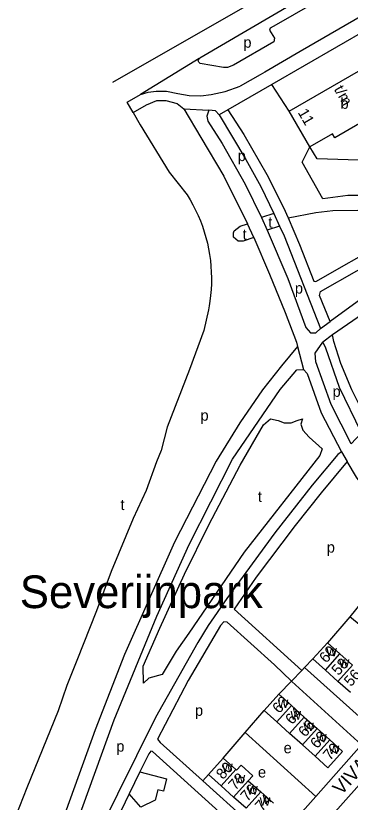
# Model space of a CAD drawing. Extents: x 159045 to 160918, y 380454 to 382516.
# Drawn here: x 159318.3 to 159441.1, y 382048.4 to 382337.4 of the extents above; entities that cross this region are included whole.
import ezdxf

# ---------------------------------------------------------------- set-up
doc = ezdxf.new("R2010")
doc.units = 0
for name, color, linetype in [('BLT_Basislijn', 7, 'Continuous'), ('BLT_Bebouwing', 7, 'Continuous'), ('BLT_Centroide', 7, 'Continuous'), ('BLT_Huisnummer', 7, 'Continuous'), ('BLT_Huisnummer_ tussenligend', 7, 'Continuous'), ('BLT_Huisnummer_reeks', 7, 'Continuous'), ('BLT_Onderverdeling_panden', 7, 'Continuous'), ('BLT_Sport_parknaam', 7, 'Continuous'), ('BLT_Straatnaam', 7, 'Continuous'), ('BLT_Vlakafsluiter', 7, 'Continuous')]:
    doc.layers.add(name, color=color, linetype=linetype)

msp = doc.modelspace()

# ---------------------------------------------------------------- linework, layer by layer
at = {"layer": 'BLT_Basislijn'}
for p, q in [((159494.14, 382393.47), (159353.79, 382312.86)), ((159512.55, 382376.27), (159422.73, 382324.31)), ((159507.03, 382367.04), (159412.29, 382312.23)), ((159420.65, 382342.17), (159385.91, 382321.89)), ((159385.58, 382321.68), (159385.91, 382321.89)), ((159422.73, 382324.31), (159409.73, 382316.76)), ((159409.73, 382316.76), (159407.99, 382315.75)), ((159407.99, 382315.75), (159400.66, 382311.52)), ((159412.29, 382312.23), (159396.13, 382302.88)), ((159418.68, 382302.38), (159412.29, 382312.23)), ((159359.18, 382305.7), (159364.06, 382308.47)), ((159361.4, 382301.85), (159361.31, 382301.8)), ((159396.13, 382302.88), (159392.96, 382301.05)), ((159428.9, 382284.85), (159426.23, 382289.25)), ((159462.69, 382283.81), (159428.9, 382284.85)), ((159374.6, 382279.99), (159381.19, 382271.64)), ((159416.59, 382267.01), (159418.25, 382263.17)), ((159413.01, 382264.77), (159408.52, 382263.36)), ((159413.01, 382264.77), (159415.11, 382260.15)), ((159408.52, 382263.36), (159410.6, 382258.69)), ((159405.64, 382256), (159403.35, 382261)), ((159415.11, 382260.15), (159410.6, 382258.69)), ((159430.17, 382222.56), (159433.75, 382225.1)), ((159434.58, 382220.18), (159431.06, 382217.46)), ((159437.83, 382177.21), (159439.91, 382173.65)), ((159445.62, 382122.3), (159440.87, 382116.62)), ((159440.87, 382116.62), (159432.69, 382107.06)), ((159427.35, 382101.11), (159424.31, 382097.97)), ((159423.26, 382096.88), (159419.49, 382092.97)), ((159424.31, 382097.97), (159423.26, 382096.88)), ((159450.05, 382074.76), (159424.31, 382097.97)), ((159419.49, 382092.97), (159414.82, 382088.15)), ((159402.54, 382074.05), (159409.44, 382082.15)), ((159394.46, 382064.58), (159402.54, 382074.05)), ((159402.54, 382074.05), (159428.38, 382050.54)), ((159445.22, 382069.48), (159428.38, 382050.54)), ((159387.02, 382056.3), (159389.08, 382058.58)), ((159387.02, 382056.3), (159412.8, 382033.08)), ((159322.34, 382053.71), (159318.3, 382043.44)), ((159412.8, 382033.08), (159428.38, 382050.54))]:
    msp.add_line(p, q, dxfattribs=at)
for points in [[(159501.17, 382387.34), (159501.9, 382387.24), (159502.71, 382386.42), (159503.24, 382384.81), (159503.24, 382382.34), (159502.64, 382380.86), (159501.42, 382379.08), (159500.46, 382378.31), (159497.68, 382376.68), (159496.51, 382377.03), (159494.66, 382380.2), (159493.96, 382380.33), (159413.82, 382334.09)], [(159592.57, 382343.04), (159590.44, 382339.54), (159588.26, 382337.01), (159584.78, 382334.23), (159580.18, 382331.31), (159560.97, 382326.03), (159552.16, 382321.45), (159546.85, 382317.26), (159543.9, 382313.98), (159537.31, 382304.44), (159532.38, 382299.35), (159524.92, 382294.23), (159519.04, 382291.75), (159461.4, 382270.09), (159448.2, 382271.36), (159440.22, 382271.36), (159430.99, 382270.17), (159423.36, 382283.59), (159426.23, 382289.25)], [(159418.25, 382263.17), (159428.39, 382265.11), (159434.66, 382265.93), (159443.56, 382265.97), (159459.49, 382265.16), (159462.83, 382265.29), (159508.3, 382282.41), (159524.15, 382288.09), (159528.25, 382289.87), (159532.86, 382292.9), (159538.43, 382297.92), (159542.44, 382303.14), (159547.33, 382310.25), (159553.12, 382315.98), (159556.64, 382318.44), (159564.66, 382322.52), (159582.73, 382326.86), (159585.81, 382328.45), (159591.54, 382332.65), (159594.65, 382336.58), (159597.52, 382341.03)], [(159413.82, 382334.09), (159411.69, 382332.86), (159411.48, 382332.18), (159413.25, 382329.18), (159413, 382327.83), (159398.22, 382319.31), (159396.04, 382318.47), (159394.58, 382318.44), (159385.93, 382319.93), (159385.45, 382320.32), (159385.23, 382320.9), (159385.58, 382321.68)], [(159418.25, 382263.17), (159422.47, 382253.34), (159427.75, 382239.88), (159428.39, 382239.82), (159453.73, 382254.29), (159461.54, 382258.1), (159522.36, 382281.45), (159530.86, 382285.26), (159544.31, 382291.88), (159569.69, 382306.51), (159584.22, 382316.36), (159597.39, 382326.49), (159609.16, 382336.32)], [(159364.06, 382308.47), (159366.94, 382309.34), (159369.88, 382309.76), (159373.62, 382309.72), (159377.78, 382308.92), (159381.94, 382308.13), (159386.17, 382307.96), (159390.04, 382308.45), (159395.11, 382309.55), (159400.66, 382311.52)], [(159361.4, 382301.85), (159366.27, 382304.65), (159370.02, 382306.28), (159373.36, 382306.34), (159377.51, 382305.13), (159380.01, 382303.17)], [(159361.4, 382301.85), (159363.99, 382297.37), (159374.6, 382279.99)], [(159380.01, 382303.17), (159386.25, 382292.64)], [(159389.22, 382302.69), (159388.4, 382300.52), (159388.85, 382298.67)], [(159392.96, 382301.05), (159391.63, 382302.5), (159389.22, 382302.69)], [(159396.13, 382302.88), (159402.02, 382293.8), (159410.5, 382279.16), (159416.59, 382267.01)], [(159392.96, 382301.05), (159402.77, 382284.64), (159408.25, 382274.7), (159413.01, 382264.77)], [(159388.85, 382298.67), (159394.04, 382290.45), (159402.47, 382275.5), (159408.52, 382263.36)], [(159386.25, 382292.64), (159394.67, 382278.52), (159403.35, 382261)], [(159381.19, 382271.64), (159382.31, 382269.8), (159383.35, 382267.93), (159384.33, 382266.01), (159385.23, 382264.06), (159386.06, 382262.08), (159386.81, 382260.07), (159387.49, 382258.03), (159388.1, 382255.97), (159388.62, 382253.89), (159389.07, 382251.79), (159389.44, 382249.67), (159389.73, 382247.54), (159389.94, 382245.4), (159390.07, 382243.26), (159390.12, 382241.11), (159390.1, 382238.96), (159389.99, 382236.82), (159389.8, 382234.68), (159389.53, 382232.55), (159389.25, 382230.79)], [(159433.75, 382225.1), (159429.82, 382234.7), (159430.2, 382236.06), (159443.48, 382243.73), (159460.6, 382252.85), (159474.82, 382258.74), (159507, 382269.81), (159508.24, 382269.6), (159513.86, 382263.59)], [(159513.86, 382263.59), (159504.57, 382259.78), (159475.84, 382249.58), (159459.14, 382241.72), (159444.96, 382233.32), (159433.75, 382225.1)], [(159405.64, 382256), (159401.76, 382254.66), (159399.9, 382254.6), (159398.24, 382256.09), (159398.17, 382257.62), (159398.47, 382258.38), (159400.62, 382260.07), (159403.35, 382261)], [(159410.6, 382258.69), (159418.11, 382240.9), (159424.77, 382222.88), (159426.48, 382220.96), (159428.48, 382220.91), (159430.17, 382222.56)], [(159415.11, 382260.15), (159416.78, 382256.54), (159430.17, 382222.56)], [(159517.65, 382260.05), (159525, 382252.54), (159525, 382252.12), (159503.6, 382236.13), (159486.59, 382222.34), (159464.32, 382203.08), (159448.99, 382187.66), (159448.36, 382187.58), (159447.53, 382188.28), (159441.59, 382199.97), (159437.61, 382209.67), (159435.01, 382217.76), (159434.58, 382220.18)], [(159517.65, 382260.05), (159479.27, 382245.99), (159474.5, 382243.85), (159454.62, 382233.99), (159434.58, 382220.18)], [(159405.64, 382256), (159411.49, 382242.52), (159417.17, 382228.38), (159421.39, 382217.46), (159421.69, 382215.85)], [(159389.25, 382230.79), (159389.01, 382229.34), (159387.3, 382221.73), (159382.01, 382207.45), (159373.92, 382186.32), (159371.65, 382177.7)], [(159421.69, 382215.85), (159415.79, 382208.81), (159408.92, 382199.96), (159400.59, 382187.82), (159391.83, 382173.72), (159376.55, 382143.99), (159358.26, 382102.74), (159347.5, 382075.04), (159336.81, 382045.51), (159335.16, 382040.3)], [(159441.46, 382180.13), (159434.11, 382194.56), (159428.39, 382210.3), (159428.23, 382213.48), (159431.06, 382217.46)], [(159431.06, 382217.46), (159432.01, 382215.41), (159436.97, 382200.92), (159444.92, 382184.55), (159444.96, 382183.94), (159441.46, 382180.13)], [(159348.67, 382037.27), (159341.56, 382037.74), (159340.45, 382039.52), (159340.45, 382040.16), (159354.44, 382078.73), (159370.08, 382116.79), (159381.97, 382143.1), (159397.86, 382174.46), (159415.4, 382200.16), (159421.45, 382207.36), (159423.93, 382207.44)], [(159423.93, 382207.44), (159425.21, 382206.01), (159430.45, 382191.54), (159437.83, 382177.21)], [(159371.65, 382177.7), (159370, 382173.51), (159366.12, 382163.01), (159361.34, 382152.69)], [(159437.83, 382177.21), (159436.45, 382176.18), (159427.13, 382164.93), (159413.36, 382147.49), (159395.71, 382123.28), (159388.95, 382113.4), (159385.13, 382107.2), (159369.55, 382079.59), (159348.67, 382037.27)], [(159439.91, 382173.65), (159430.45, 382162.19), (159420.79, 382150.14), (159406.49, 382131.2), (159398.46, 382119.33), (159423.26, 382096.88)], [(159473.33, 382132.75), (159464.63, 382141.49), (159454.94, 382151.94), (159443.35, 382167.93), (159439.91, 382173.65)], [(159361.34, 382152.69), (159353.38, 382133.22), (159347.91, 382118.74), (159340.69, 382100.49)], [(159419.49, 382092.97), (159413.27, 382098.99), (159395.86, 382114.62), (159394.61, 382114.78), (159393.5, 382113.41), (159381.64, 382093.2), (159370.29, 382071.58), (159371.33, 382070.37), (159386.9, 382056.41), (159387.02, 382056.3)], [(159466.71, 382093.52), (159446.24, 382112.11), (159440.87, 382116.62)], [(159340.69, 382100.49), (159337.01, 382091.36), (159333.82, 382082.04), (159322.34, 382053.71)], [(159445.22, 382069.48), (159419.61, 382092.85), (159419.49, 382092.97)], [(159409.77, 382029.71), (159368.44, 382067.04), (159367.87, 382067.22), (159367.16, 382066.23), (159363.9, 382059.57)], [(159363.9, 382059.57), (159373.68, 382056.99), (159372.49, 382052.5), (159370.48, 382053.03), (159369.48, 382049.24), (159364.19, 382046.58), (159359.96, 382051.54)], [(159363.9, 382059.57), (159359.96, 382051.54)], [(159445.41, 382056.01), (159420.6, 382028.1), (159419.67, 382026.94)], [(159359.96, 382051.54), (159356.94, 382045.38), (159353.22, 382036.77)]]:
    msp.add_lwpolyline(points, dxfattribs=at)
msp.add_lwpolyline([(159423.5, 382189.3), (159422.89, 382187.38), (159423.67, 382185.22), (159425.96, 382182.54), (159430.76, 382178.32), (159429.91, 382175.83), (159402.15, 382140.33), (159381.86, 382110.52), (159377.16, 382103.9), (159372.05, 382095.43), (159367.17, 382094.07), (159365.14, 382092.19), (159365.06, 382098.42), (159371.18, 382112.41), (159380.22, 382132.24), (159389.22, 382150.42), (159400.61, 382172.28), (159409.27, 382187.12), (159411.82, 382189.35), (159414.66, 382188.66), (159416.77, 382187.85), (159419.43, 382187.82), (159421.56, 382188.66)], close=True, dxfattribs=at)
at = {"layer": 'BLT_Bebouwing'}
for p, q in [((159427.35, 382101.11), (159432.69, 382107.06)), ((159432.69, 382107.06), (159437.28, 382102.93)), ((159437.28, 382102.93), (159441.88, 382098.81)), ((159431.94, 382096.98), (159427.35, 382101.11)), ((159436.54, 382092.86), (159431.94, 382096.98)), ((159441.13, 382088.73), (159436.54, 382092.86)), ((159409.44, 382082.15), (159414.82, 382088.15)), ((159414.82, 382088.15), (159419.51, 382083.94)), ((159414.12, 382077.94), (159409.44, 382082.15)), ((159419.51, 382083.94), (159424.19, 382079.74)), ((159424.19, 382079.74), (159428.88, 382075.53)), ((159418.81, 382073.74), (159414.12, 382077.94)), ((159423.49, 382069.53), (159418.81, 382073.74)), ((159428.88, 382075.53), (159433.56, 382071.33)), ((159428.18, 382065.33), (159423.49, 382069.53)), ((159389.08, 382058.58), (159394.46, 382064.58)), ((159394.46, 382064.58), (159399.05, 382060.45)), ((159393.67, 382054.46), (159389.08, 382058.58)), ((159403.65, 382056.33), (159408.24, 382052.21)), ((159398.27, 382050.33), (159393.67, 382054.46)), ((159402.86, 382046.21), (159398.27, 382050.33)), ((159408.24, 382052.21), (159412.84, 382048.08))]:
    msp.add_line(p, q, dxfattribs=at)
for points in [[(159418.68, 382302.38), (159453.66, 382322.57), (159461.24, 382309.46), (159447.4, 382301.46), (159448.22, 382300.04), (159435.38, 382292.63), (159434.56, 382294.05), (159426.23, 382289.25)], [(159426.23, 382289.25), (159418.68, 382302.38)], [(159433.56, 382071.33), (159438.24, 382067.12), (159432.86, 382061.12), (159428.18, 382065.33)], [(159399.05, 382060.45), (159399.29, 382060.24), (159400.97, 382062.1), (159405.32, 382058.17), (159403.65, 382056.33)]]:
    msp.add_lwpolyline(points, dxfattribs=at)
at = {"layer": 'BLT_Onderverdeling_panden'}
for p, q in [((159431.94, 382096.98), (159437.28, 382102.93)), ((159436.54, 382092.86), (159441.88, 382098.81)), ((159414.12, 382077.94), (159419.51, 382083.94)), ((159418.81, 382073.74), (159424.19, 382079.74)), ((159423.49, 382069.53), (159428.88, 382075.53)), ((159428.18, 382065.33), (159433.56, 382071.33)), ((159393.67, 382054.46), (159399.05, 382060.45)), ((159398.27, 382050.33), (159403.65, 382056.33)), ((159402.86, 382046.21), (159408.24, 382052.21))]:
    msp.add_line(p, q, dxfattribs=at)
at = {"layer": 'BLT_Vlakafsluiter'}
for p, q in [((159385.58, 382321.68), (159364.06, 382308.47)), ((159361.4, 382301.85), (159359.18, 382305.7)), ((159380.01, 382303.17), (159389.22, 382302.69)), ((159421.69, 382215.85), (159423.93, 382207.44))]:
    msp.add_line(p, q, dxfattribs=at)

# ---------------------------------------------------------------- texts
at = {"layer": 'BLT_Centroide'}
for s, p in [('p', (159401.85, 382325.69)), ('b', (159437.49, 382303.24)), ('p', (159399.76, 382284.03)), ('t', (159410.99, 382259.59)), ('t', (159401.58, 382255.11)), ('p', (159420.74, 382235.35)), ('p', (159434.57, 382197.41)), ('p', (159386.1, 382188.63)), ('t', (159407.15, 382158.78)), ('t', (159356.73, 382155.8)), ('p', (159432.46, 382140.17)), ('w', (159432.31, 382102.03)), ('w', (159436.91, 382097.91)), ('w', (159414.47, 382083.05)), ('p', (159384.09, 382080.2)), ('w', (159419.16, 382078.84)), ('w', (159423.84, 382074.64)), ('w', (159428.53, 382070.44)), ('p', (159355.22, 382067.05)), ('e', (159416.61, 382066.45)), ('w', (159433.2, 382066.22)), ('w', (159394.06, 382059.52)), ('e', (159407.2, 382057.53)), ('w', (159398.66, 382055.41)), ('w', (159403.25, 382051.28)), ('w', (159407.84, 382047.16))]:
    msp.add_text(s, height=4, dxfattribs=at).set_placement(p)
at = {"layer": 'BLT_Huisnummer'}
for s, rotation, p in [('60', 48.0975, (159432.24, 382099.32)), ('56', 48.0932, (159441.32, 382090.69)), ('62', 48.0926, (159415.02, 382080.81)), ('66', 48.0931, (159424.52, 382072.13)), ('70', 48.0926, (159433.6, 382063.57)), ('80', 48.0947, (159394.37, 382056.56)), ('76', 48.0953, (159403.32, 382048.47))]:
    msp.add_text(s, height=4, rotation=rotation, dxfattribs=at).set_placement(p)
at = {"layer": 'BLT_Huisnummer_ tussenligend'}
for s, rotation, p in [('58', 48.0932, (159436.74, 382094.77)), ('64', 48.0926, (159419.76, 382076.73)), ('68', 48.0931, (159428.93, 382067.9)), ('78', 48.0953, (159398.92, 382052.55)), ('74', 48.0947, (159408.68, 382044.82))]:
    msp.add_text(s, height=4, rotation=rotation, dxfattribs=at).set_placement(p)
at = {"layer": 'BLT_Huisnummer_reeks'}
for s, rotation, p in [('t/m', 300.0345, (159434.95, 382310.45)), ('11', 299.8992, (159421.7, 382301.92))]:
    msp.add_text(s, height=4, rotation=rotation, dxfattribs=at).set_placement(p)
at = {"layer": 'BLT_Sport_parknaam'}
msp.add_text('Severijnpark', height=12, dxfattribs=at).set_placement((159319.78, 382119.77))
at = {"layer": 'BLT_Straatnaam'}
msp.add_text('VIVALDISTRAAT', height=5, rotation=47.8952, dxfattribs=at).set_placement((159437.81, 382050.82))

doc.saveas('drawing.dxf')
